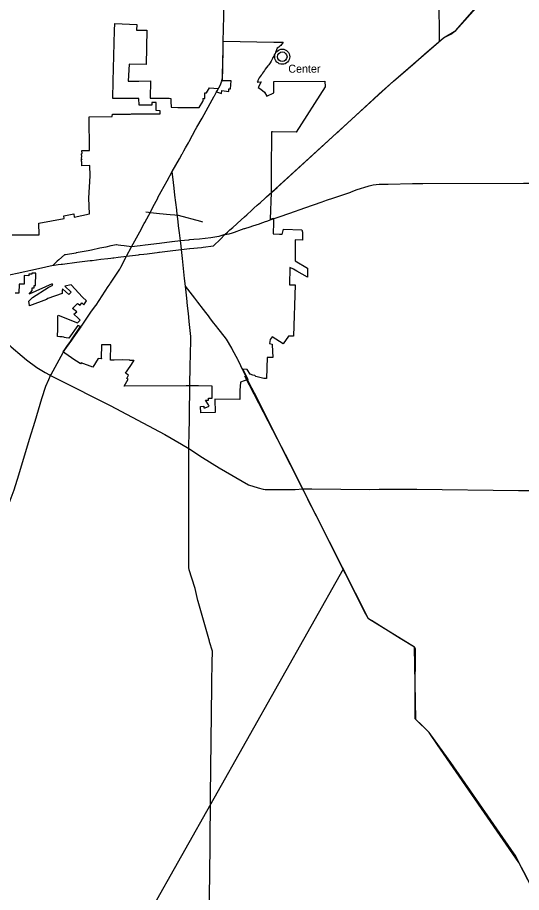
# Model space of a CAD drawing. Extents: x 0 to 882, y 0 to 440.
# Drawn here: x 287.2 to 352.8, y 123.7 to 237.6 of the extents above; entities that cross this region are included whole.
import ezdxf

# ---------------------------------------------------------------- set-up
doc = ezdxf.new("R2010")
doc.units = 0
for name, color, linetype in [('DV_X_Corp_Line', 7, 'Continuous'), ('GM_X_Rail_Line', 7, 'Continuous'), ('GM_X_State_Route', 7, 'Continuous'), ('GM_X_US_Route', 7, 'Continuous'), ('RD_P_Fence', 7, 'Continuous'), ('SH_Data', 7, 'Continuous')]:
    doc.layers.add(name, color=color, linetype=linetype)

msp = doc.modelspace()

# ---------------------------------------------------------------- linework, layer by layer
at = {"layer": 'DV_X_Corp_Line'}
msp.add_lwpolyline([(286.52, 209.28), (287.46, 209.28), (288.37, 209.28), (289.3, 209.28), (289.93, 209.29), (290.07, 209.31), (290.03, 210.81), (293.32, 211.42), (293.25, 211.77), (294.56, 212.01), (294.6, 211.61), (296.58, 212.01), (296.53, 214.09), (296.68, 216.97), (296.66, 218.31), (295.61, 218.29), (295.61, 218.86), (295.54, 218.85), (295.54, 219.13), (295.59, 219.08), (295.57, 219.38), (295.61, 219.43), (295.58, 219.83), (295.63, 219.88), (295.62, 220.29), (296.59, 220.27), (296.58, 220.32), (296.57, 224.67), (299.56, 224.7), (299.58, 225), (301.88, 225), (301.89, 225.02), (301.91, 225.02), (301.95, 225.02), (302.07, 225.03), (303.05, 225.03), (303.75, 225.04), (304.4, 225.04), (305.16, 225.05), (305.78, 225.05), (305.8, 225.45), (305.26, 225.46), (305.27, 226.52), (304.72, 226.51), (304.72, 226.16), (303.04, 226.18), (303.03, 227.06), (299.62, 227.05), (299.67, 229.29), (299.84, 235.88), (299.88, 236.8), (302.74, 236.69), (302.73, 235.93), (304.07, 235.93), (303.99, 231.47), (301.74, 231.51), (301.63, 229.3), (303.01, 229.31), (304.54, 229.32), (304.51, 227.08), (306.97, 227.07), (307.19, 227.06), (307.2, 226.64), (307.21, 225.91), (308.08, 225.89), (308.86, 225.87), (310.86, 225.85), (311.34, 226.65), (311.45, 226.9), (311.33, 227.06), (311.6, 227.04), (311.62, 227.79), (311.84, 227.79), (312.2, 228.41), (313.33, 228.33), (313.1, 227.91), (313.78, 227.7), (313.81, 228.08), (314.71, 227.96), (314.72, 228.32), (314.95, 228.32), (315.01, 229.33), (313.81, 229.33), (313.86, 229.56), (313.88, 229.7), (313.89, 229.83), (313.89, 229.89), (313.9, 230.2), (313.97, 233.01), (313.98, 233.55), (314, 234.5), (320.59, 234.36), (321.78, 234.36), (321.48, 233.96), (321.37, 233.87), (321.21, 233.74), (321.02, 233.58), (320.93, 233.39), (320.86, 233.25), (320.79, 233.07), (320.73, 232.91), (320.64, 232.72), (320.56, 232.57), (320.46, 232.36), (320.4, 232.23), (320.32, 232.06), (320.22, 231.89), (320.1, 231.7), (320.03, 231.57), (319.92, 231.41), (319.78, 231.28), (319.62, 231.08), (319.45, 230.85), (319.36, 230.7), (319.25, 230.51), (319.12, 230.34), (319.04, 230.21), (318.93, 230.08), (318.78, 229.91), (318.65, 229.73), (318.58, 229.54), (318.51, 229.39), (318.48, 229.25), (318.43, 229.18), (318.95, 229.19), (318.55, 228.47), (318.9, 228.27), (319.37, 227.85), (319.65, 227.36), (320.56, 227.79), (320.58, 229.26), (327.23, 229.28), (327.25, 228.56), (323.48, 222.68), (320.41, 222.7), (320.35, 222.71), (320.31, 222.72), (320.26, 222.74), (320.26, 222.67), (320.25, 217.62), (320.25, 217.06), (320.25, 216.41), (320.24, 215.75), (320.24, 215.13), (320.23, 214.79), (320.12, 211.34), (320.54, 211.48), (320.53, 210.92), (320.47, 209.41), (321.3, 209.4), (321.56, 209.39), (321.61, 209.39), (321.64, 209.38), (321.67, 209.36), (321.82, 210.04), (324.24, 209.95), (324.3, 209.64), (324.31, 208.6), (323.35, 208.63), (323.35, 205.9), (324.97, 204.96), (324.96, 203.78), (323.59, 204.55), (323.12, 204.83), (322.66, 205.06), (322.61, 202.8), (323.35, 202.78), (323.15, 196.12), (322.49, 196.11), (321.8, 195.13), (321.31, 195.43), (320.36, 196.03), (320.1, 195.66), (320.01, 195.15), (320.37, 195.08), (320.37, 194.97), (320.46, 193.34), (320.41, 193.34), (320.36, 193.33), (320.25, 193.33), (320.12, 193.32), (319.73, 193.32), (319.62, 190.61), (319.26, 190.6), (318.23, 190.87), (318.11, 191), (317.84, 191.05), (317.48, 191.15), (317.13, 191.79), (316.53, 191.81), (317.21, 190.46), (316.24, 190.14), (316.16, 189.04), (316.14, 187.86), (312.92, 187.92), (312.93, 186.16), (311.08, 186.13), (311.06, 186.97), (311.46, 186.98), (311.46, 186.8), (311.64, 186.8), (312.17, 186.98), (312.1, 187.19), (311.7, 187.77), (312.1, 187.78), (312.1, 188.04), (312.12, 188.04), (312.55, 188.05), (312.54, 188.65), (312.56, 188.65), (312.57, 188.65), (312.54, 189.62), (310.76, 189.64), (309.64, 189.64), (309.18, 189.65), (301.12, 189.62), (301.65, 190.49), (301.45, 190.6), (301.68, 191.01), (301.3, 191.29), (301.52, 191.61), (302.05, 192.42), (302.42, 192.97), (302.36, 192.95), (301.84, 192.95), (301.84, 192.98), (300.94, 193.01), (299.79, 192.98), (299.33, 192.99), (299.36, 194.99), (298.15, 194.98), (298.13, 193.3), (298.14, 193.14), (297.73, 193.21), (297.05, 192.09), (295.5, 192.63), (295.42, 192.52), (295.11, 192.72), (294.7, 193), (293.38, 193.89), (293.17, 194.05), (293.41, 194.38), (293.75, 194.89), (294.03, 195.28), (294.35, 195.74), (295.45, 197.35), (295.08, 197.5), (293.91, 195.83), (293.56, 195.91), (293.35, 195.95), (293.28, 195.96), (293.21, 195.98), (293.05, 196), (292.74, 196.04), (292.43, 196.06), (292.46, 197.06), (292.47, 197.65), (292.48, 197.73), (292.5, 198.71), (292.51, 198.86), (295.05, 197.84), (295.38, 198.2), (295.11, 198.45), (294.55, 198.95), (294.96, 199.28), (294.39, 199.7), (295.03, 200.34), (295.38, 200.13), (295.59, 200.43), (295.88, 200.2), (296.23, 200.69), (295.68, 201.17), (294.22, 202.79), (293.39, 202.61), (294.23, 201.85), (293.91, 201.51), (293.08, 202.29), (293.08, 202.14), (293.04, 202.13), (293.03, 201.68), (291.2, 201.02), (290.99, 200.9), (288.8, 200.04), (288.8, 200.12), (288.71, 200.68), (289.2, 201.14), (291.21, 202.46), (291.82, 202.76), (291.79, 202.82), (291.76, 202.93), (288.74, 201.56), (289.15, 202.04), (289.16, 202.41), (289.41, 202.39), (289.42, 202.7), (289.57, 202.69), (289.62, 204.3), (289.08, 204.3), (289.08, 204.18), (288.71, 204.19), (288.71, 203.98), (288.12, 204), (288.09, 202.88), (287.45, 202.89), (287.43, 201.7), (286.94, 201.72)], dxfattribs=at)
for radius in [0.982, 0.623]:
    msp.add_circle((321.67, 232.48), radius, dxfattribs=at)
at = {"layer": 'GM_X_Rail_Line'}
msp.add_lwpolyline([(303.94, 212.31), (304.94, 212.15), (305.69, 212.08), (307.11, 211.96), (307.71, 211.9), (308.13, 211.84), (311.04, 211.06), (311.31, 210.98)], dxfattribs=at)
at = {"layer": 'GM_X_State_Route'}
for points in [[(313.98, 234.41), (313.98, 234.46), (314.14, 241.1), (314.16, 242.6), (314.49, 254.55), (314.58, 255.73), (314.42, 264.05), (314.41, 268.18), (315.07, 281.53), (315.28, 290.21)], [(333.52, 226.93), (334.3, 227.65), (336.15, 229.28), (338, 230.9), (338.98, 231.73), (340.18, 232.8), (342.65, 234.94), (343.59, 235.43), (343.96, 235.66), (344.25, 235.91), (348.44, 240.75)], [(313.78, 229.2), (313.85, 229.35), (313.89, 229.55), (313.93, 230.91), (313.98, 234.41)], [(313.19, 228.04), (313.19, 228.04), (313.62, 228.83), (313.78, 229.2)], [(312.81, 227.35), (312.84, 227.41), (313.06, 227.81)], [(313.06, 227.81), (313.19, 228.04)], [(311.24, 224.5), (311.24, 224.5), (312.02, 225.92), (312.81, 227.35)], [(329.02, 222.78), (333.52, 226.93)], [(308.66, 219.82), (308.7, 219.89), (308.89, 220.24), (309.1, 220.62), (309.46, 221.26), (309.56, 221.45), (310.01, 222.27), (310.4, 222.99), (310.57, 223.3), (311.24, 224.5)], [(321, 215.47), (327.1, 221.02), (328.82, 222.6), (329.02, 222.78)], [(305.51, 214.15), (305.93, 214.92), (306.33, 215.65), (306.69, 216.33), (307.36, 217.56), (308.29, 219.17), (308.66, 219.82)], [(307.97, 212.39), (307.97, 212.4), (307.96, 212.43), (307.95, 212.57), (307.84, 213.5), (307.72, 214.45), (307.61, 215.39), (307.53, 216.11), (307.36, 217.56)], [(320.32, 214.85), (321, 215.47)], [(330.58, 214.87), (330.64, 214.89), (331.41, 215.19), (332.84, 215.64)], [(332.84, 215.64), (332.86, 215.65), (332.97, 215.69), (333.5, 215.81), (334.27, 215.88), (335.42, 215.91), (335.44, 215.91)], [(335.44, 215.91), (338.63, 215.99), (339.95, 215.99), (353.06, 216.02), (353.75, 216.02)], [(303.79, 210.9), (304.3, 211.86), (304.78, 212.77), (304.85, 212.89), (305.47, 214.07), (305.49, 214.11), (305.51, 214.15)], [(314.19, 209.33), (314.56, 209.66), (314.86, 209.94), (315.23, 210.27), (316.35, 211.27), (316.78, 211.66), (317.05, 211.91), (317.71, 212.5), (317.99, 212.75), (318.42, 213.14), (318.83, 213.51), (319.46, 214.08), (319.63, 214.23), (319.64, 214.24)], [(319.64, 214.24), (320.31, 214.84), (320.32, 214.85)], [(327.57, 213.84), (328.25, 214.06), (330.58, 214.87)], [(320.23, 211.29), (320.48, 211.38), (321.27, 211.64), (322.65, 212.12), (324.61, 212.8), (326.85, 213.59), (327.09, 213.67)], [(327.09, 213.67), (327.57, 213.84)], [(309.08, 202.63), (308.97, 203.63), (308.69, 206.23), (308.57, 207.37), (308.51, 207.85), (308.43, 208.51), (308.31, 209.55), (308.19, 210.49), (308.13, 211.02), (307.97, 212.39)], [(302.05, 207.74), (303.13, 209.7), (303.72, 210.78), (303.79, 210.9)], [(315.45, 209.63), (316.38, 209.97), (316.74, 210.1), (316.79, 210.12), (317.52, 210.33), (317.86, 210.45), (318.72, 210.75), (318.82, 210.79), (319.48, 211.02), (319.65, 211.08), (320.23, 211.29)], [(314.19, 209.33), (314.75, 209.44), (315.19, 209.54), (315.45, 209.63)], [(309.62, 208.64), (309.49, 208.62), (308.43, 208.51), (307.37, 208.38), (307.37, 208.38)], [(310.93, 208.75), (310.91, 208.75), (310.18, 208.7), (309.62, 208.64)], [(309.65, 207.51), (311.15, 207.65), (311.37, 207.68), (312.73, 207.86), (313.63, 208.75), (314.19, 209.33)], [(314.19, 209.33), (313.43, 209.1), (312.37, 208.91), (310.93, 208.75)], [(302.05, 207.74), (301.11, 207.86), (300.67, 207.92), (300.34, 207.96), (300.13, 207.98), (300.05, 207.99), (299.43, 207.86), (299.38, 207.85), (298.74, 207.71), (297.96, 207.54), (296.84, 207.29), (296.43, 207.2), (294.85, 206.94), (294.81, 206.93)], [(301.4, 206.51), (301.4, 206.51), (302.05, 207.74)], [(307.37, 208.38), (307.29, 208.37), (305.7, 208.18), (303.86, 207.96), (303.2, 207.88), (302.05, 207.74)], [(305.7, 207.03), (307.44, 207.24), (308.57, 207.37), (309.62, 207.51), (309.63, 207.51), (309.65, 207.51)], [(294.81, 206.93), (293.48, 206.71), (293.33, 206.69), (292.59, 206.05), (292.4, 205.88), (291.86, 205.34)], [(292.91, 205.48), (293.1, 205.5), (294.94, 205.72), (296.69, 205.94), (296.86, 205.96), (296.96, 205.97), (298.09, 206.11), (298.97, 206.22), (299.37, 206.27), (299.62, 206.3), (299.76, 206.31), (300.31, 206.38), (301.4, 206.51)], [(300.67, 205.09), (301.4, 206.51)], [(301.4, 206.51), (302.97, 206.7), (303.11, 206.72), (303.67, 206.78), (304.08, 206.83), (305.05, 206.95), (305.42, 206.99), (305.63, 207.02), (305.7, 207.03), (305.7, 207.03)], [(283.25, 203.53), (283.25, 203.53), (284.65, 203.84), (286.35, 204.13), (287.21, 204.31), (288.2, 204.52), (288.95, 204.68), (289.98, 204.91), (291.86, 205.34), (292, 205.36)], [(292, 205.36), (292.52, 205.43), (292.52, 205.43)], [(292.52, 205.43), (292.91, 205.48), (292.91, 205.48)], [(297.4, 200.09), (297.45, 200.16), (299.03, 202.56), (299.29, 202.94), (299.33, 203.01), (300.27, 204.43), (300.55, 204.84), (300.59, 204.92), (300.67, 205.08), (300.67, 205.09)], [(312.21, 198.55), (312.2, 198.57), (311.42, 199.58), (310.7, 200.52), (310.29, 201.05), (309.08, 202.63)], [(309.25, 201.06), (309.25, 201.06), (309.08, 202.63)], [(309.57, 198.05), (309.57, 198.05), (309.46, 199.07), (309.35, 200.07), (309.25, 201.06)], [(295.53, 197.34), (295.58, 197.41), (295.83, 197.8), (296.77, 199.24), (297.39, 200.06), (297.4, 200.09)], [(315.93, 192.97), (315.88, 193.07), (315.22, 194.34), (315.15, 194.47), (315.11, 194.53), (314.4, 195.7), (313.63, 196.71), (313.45, 196.95), (312.99, 197.55), (312.79, 197.8), (312.21, 198.55)], [(295.3, 197.01), (295.53, 197.34)], [(309.69, 192.27), (309.69, 192.27), (309.69, 192.42), (309.72, 193.55), (309.78, 195.82), (309.78, 196.08), (309.66, 197.24), (309.58, 198), (309.57, 198.05)], [(293.63, 194.63), (294.32, 195.59), (294.41, 195.71), (295.3, 197.01)], [(291.6, 191.1), (291.6, 191.1), (293.18, 193.98), (293.18, 193.98)], [(293.18, 193.98), (293.41, 194.31), (293.63, 194.63)], [(316.56, 191.67), (316.28, 192.24), (315.93, 192.97)], [(309.65, 189.63), (309.69, 192.27)], [(318.4, 188.02), (317.39, 190.01), (316.57, 191.66), (316.56, 191.67)], [(288.8, 182.71), (289.52, 185.05), (290.41, 188.01), (290.91, 189.59), (291.3, 190.45), (291.54, 190.99)], [(291.54, 190.99), (291.6, 191.1)], [(309.58, 183.84), (309.6, 184.9), (309.61, 185.7), (309.61, 186.22), (309.62, 187.27), (309.63, 188.16), (309.65, 189.04), (309.65, 189.55), (309.65, 189.63)], [(321.07, 182.72), (321.01, 182.84), (318.45, 187.92), (318.4, 188.02)], [(309.54, 181.47), (309.58, 183.84)], [(285.9, 173.66), (286.82, 176.09), (287.41, 178.05), (288.8, 182.71)], [(323.76, 177.4), (322.6, 179.7), (321.07, 182.72)], [(310.3, 163.38), (309.57, 165.71), (309.52, 166.01), (309.52, 174.21), (309.54, 176.21), (309.54, 176.33), (309.54, 178.16), (309.54, 181.47)], [(324.35, 176.22), (323.76, 177.4)], [(325, 174.87), (324.35, 176.22)], [(329.91, 165.19), (325.94, 173.04), (325.01, 174.84), (325, 174.87)], [(331.21, 162.62), (329.91, 165.19)], [(310.72, 161.56), (310.68, 161.71), (310.34, 163.25), (310.3, 163.38)], [(339.05, 146.23), (338.96, 146.32), (338.95, 149.45), (339.02, 155.41), (338.86, 155.61), (337.01, 156.77), (333.27, 159.08), (332.91, 159.33), (332.39, 160.22), (331.21, 162.62)], [(312.23, 156.32), (312.21, 156.39), (310.72, 161.56)], [(312.11, 116.42), (312.31, 129.67), (312.36, 136.32), (312.5, 150.5), (312.51, 150.79), (312.57, 153.89), (312.59, 154.82), (312.59, 155.09), (312.23, 156.32)], [(351.84, 128.73), (346.53, 136.35), (343.59, 140.62), (340.8, 144.52), (339.84, 145.46), (339.05, 146.23)], [(354.24, 124.19), (353.63, 125.39), (353.45, 125.75), (353.1, 126.4), (352.46, 127.61), (352, 128.51), (351.84, 128.73)]]:
    msp.add_lwpolyline(points, dxfattribs=at)
at = {"layer": 'GM_X_US_Route'}
for points in [[(284.75, 196.25), (285.12, 195.91), (285.78, 195.31), (286.39, 194.74), (287.86, 193.49), (288.42, 193.01), (289.75, 192.02), (290.82, 191.38), (291.41, 191.06)], [(291.41, 191.06), (291.41, 191.05), (291.54, 190.99)], [(291.54, 190.99), (292.49, 190.5), (292.49, 190.5)], [(292.49, 190.5), (299.27, 187.09), (306.42, 183.32), (308.56, 182.04), (309.54, 181.47)], [(309.54, 181.47), (311.31, 180.33), (313.48, 178.97), (317.27, 176.76), (318.56, 176.35), (319.17, 176.21), (319.47, 176.15), (319.71, 176.13), (323.35, 176.14), (324.35, 176.22)], [(324.35, 176.22), (324.62, 176.22)], [(324.62, 176.22), (325.54, 176.22)], [(325.54, 176.22), (333.06, 176.17), (334.26, 176.18)], [(334.26, 176.18), (335.84, 176.19), (336.78, 176.19)], [(336.78, 176.19), (339.2, 176.18), (352.42, 176.04), (352.6, 176.04), (365.54, 176.01), (365.95, 176.01), (383.03, 176.07)]]:
    msp.add_lwpolyline(points, dxfattribs=at)
at = {"layer": 'RD_P_Fence'}
for points in [[(320.32, 214.85), (336.15, 229.28), (342.65, 234.94), (344.25, 235.91), (357.18, 250.34)], [(364.27, 96.7), (357.65, 109.93), (354.78, 115.84), (353.74, 121.33), (354.24, 124.19), (352.46, 127.61), (341.85, 142.9), (340.8, 144.52), (339.05, 146.23), (338.86, 155.61), (332.91, 159.33), (321.07, 182.72), (316.82, 190.88)]]:
    msp.add_lwpolyline(points, dxfattribs=at)
at = {"layer": 'SH_Data'}
for p, q in [((341.34, 343.45), (342.09, 234.45)), ((288.13, 92.15), (329.62, 165.82))]:
    msp.add_line(p, q, dxfattribs=at)

# ---------------------------------------------------------------- texts
at = {"layer": 'DV_X_Corp_Line'}
msp.add_text('Center', height=1.042, rotation=0, dxfattribs=at).set_placement((322.46, 230.4))

doc.saveas('drawing.dxf')
